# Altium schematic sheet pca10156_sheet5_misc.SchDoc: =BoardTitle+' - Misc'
size A3; Organization: Nordic Semiconductor; DocumentNumber: 5; SheetNumber: 5; SheetTotal: 8; CompanyName: Nordic Semiconductor; DocumentSize: A4
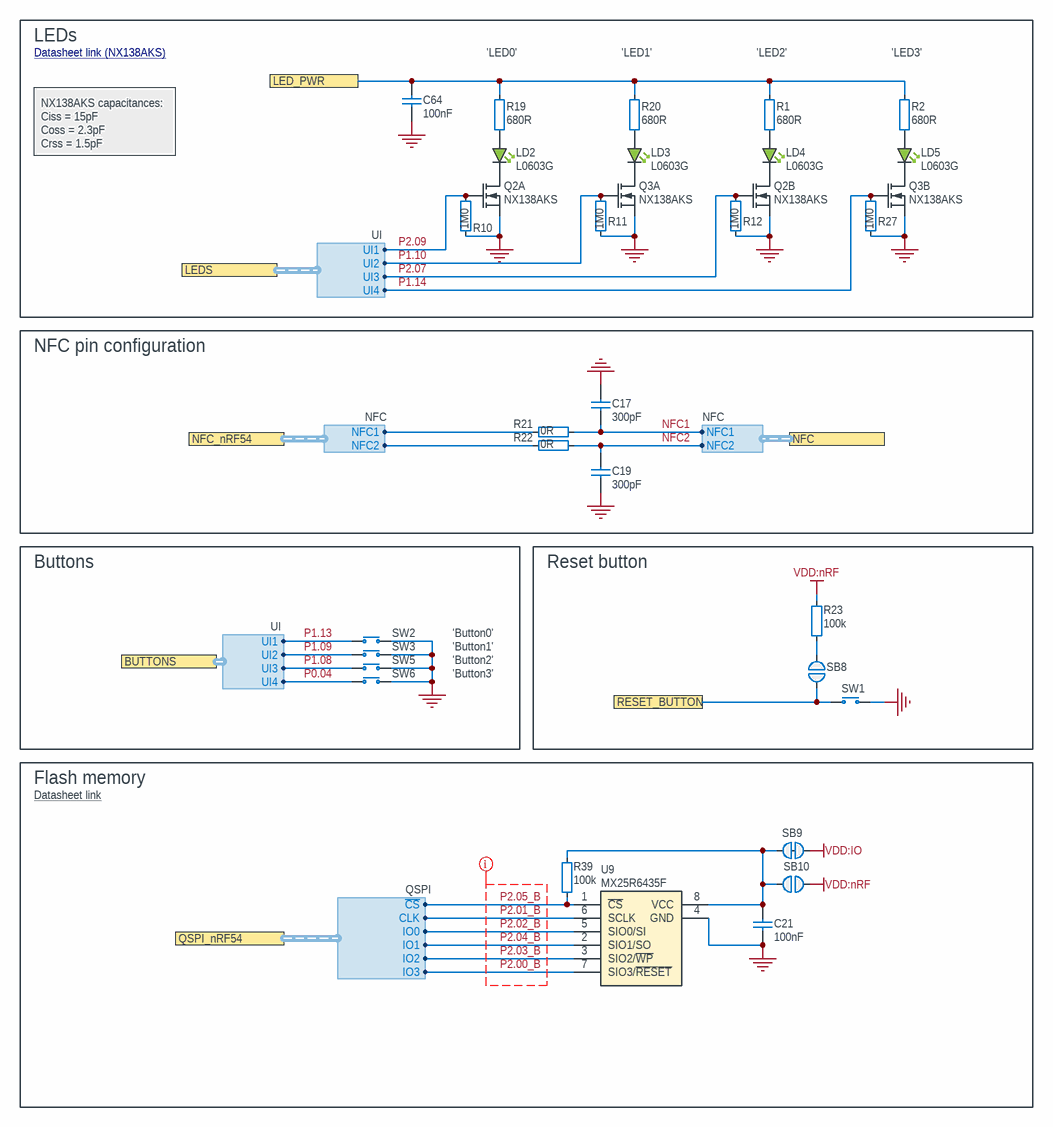
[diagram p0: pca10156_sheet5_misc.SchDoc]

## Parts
C17  300pF  [CAPC1005X04L]
C19  300pF  [CAPC1005X04L]
C21  100nF  [CAPC0603X03L_C]
C64  100nF  [CAPC0603X03L_C]
LD2  L0603G  [LED_0603_G]
LD3  L0603G  [LED_0603_G]
LD4  L0603G  [LED_0603_G]
LD5  L0603G  [LED_0603_G]
Q2  NX138AKS  [TSSOP6]  (parts A,B of 2)
Q3  NX138AKS  [TSSOP6]  (parts A,B of 2)
R1  680R  [RESC0603X03L_C]
R2  680R  [RESC0603X03L_C]
R10  1M0  [RESC0603X03L_C]
R11  1M0  [RESC0603X03L_C]
R12  1M0  [RESC0603X03L_C]
R19  680R  [RESC0603X03L_C]
R20  680R  [RESC0603X03L_C]
R21  0R  [RESC1005X04L]
R22  0R  [RESC1005X04L]
R23  100k  [RESC0603X03L_C]
R27  1M0  [RESC0603X03L_C]
R39  100k  [RESC0603X03L_C]
SB8  Solderbridge  [Solderbridge]  (value not drawn)  (no BOM)
SB9  Solderbridge  [Solderbridge_Shorted]  (value not drawn)  (net tie, no BOM)
SB10  Solderbridge  [Solderbridge]  (value not drawn)  (no BOM)
SW1  PB SW  [Switch-PB-6.2x6.3mm-SMD]  (value not drawn)
SW2  PB SW  [Switch-PB-6.2x6.3mm-SMD]  (value not drawn)
SW3  PB SW  [Switch-PB-6.2x6.3mm-SMD]  (value not drawn)
SW5  PB SW  [Switch-PB-6.2x6.3mm-SMD]  (value not drawn)
SW6  PB SW  [Switch-PB-6.2x6.3mm-SMD]  (value not drawn)
U9  MX25R6435F  [SON127P600X80_HS-9N]

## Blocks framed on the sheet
LEDs: C64 LD2-LD5 Q2 Q3 R1 R2 R10-R12 R19 R20 R27
NFC pin configuration: C17 C19 R21 R22
Buttons: SW2 SW3 SW5 SW6
Reset button: R23 SB8 SW1
Flash memory: C21 R39 SB9 SB10 U9

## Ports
BUTTONS (harness UI), LED_PWR, LEDS (harness UI), NFC (harness NFC), NFC_nRF54 (harness NFC), QSPI_nRF54 (harness QSPI), RESET_BUTTON

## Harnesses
NFC: NFC2, NFC1
UI: UI2, UI1, UI3, UI4
UI: UI2, UI3, UI4, UI1
QSPI: ~{CS}, IO0, CLK, IO1, IO2, IO3

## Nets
GND: C17.2 C19.1 C21.2 C64.1 Q2.1(S1) Q2.4(S2) Q3.1(S1) Q3.4(S2) R10.2 R11.2 R12.2 R27.2 SW1.1(N.O) SW2.1(N.O) SW3.1(N.O) SW5.1(N.O) SW6.1(N.O) U9.4(GND) U9.9(GND)
VDD:IO: SB9.1
VDD:nRF: R23.2 SB10.1
LED_PWR: C64.2 R1.2 R2.2 R19.2 R20.2 ; port LED_PWR
NFC1: C17.1 R21.2 ; port NFC.NFC1
NFC2: C19.2 R22.2 ; port NFC.NFC2
P0.04: SW6.2(COM) ; port BUTTONS.UI4
P1.08: SW5.2(COM) ; port BUTTONS.UI3
P1.09: SW3.2(COM) ; port BUTTONS.UI2
P1.10: Q3.2(G1) R11.1 ; port LEDS.UI2
P1.13: SW2.2(COM) ; port BUTTONS.UI1
P1.14: Q3.5(G2) R27.1 ; port LEDS.UI4
P2.00_B: U9.7(SIO3/~{RESET}) ; port QSPI_nRF54.IO3
P2.01_B: U9.6(SCLK) ; port QSPI_nRF54.CLK
P2.02_B: U9.5(SIO0/SI) ; port QSPI_nRF54.IO0
P2.03_B: U9.3(SIO2/~{WP}) ; port QSPI_nRF54.IO2
P2.04_B: U9.2(SIO1/SO) ; port QSPI_nRF54.IO1
P2.05_B: R39.1 U9.1(~{CS}) ; port QSPI_nRF54.~{CS}
P2.07: Q2.5(G2) R12.1 ; port LEDS.UI3
P2.09: Q2.2(G1) R10.1 ; port LEDS.UI1
RESET_BUTTON: SB8.1 SW1.2(COM) ; port RESET_BUTTON
NetC21_1: C21.1 R39.2 SB9.2 SB10.2 U9.8(VCC)
NetLD2_1: LD2.1(C) Q2.6(D1)
NetLD2_2: LD2.2(A) R19.1
NetLD3_1: LD3.1(C) Q3.6(D1)
NetLD3_2: LD3.2(A) R20.1
NetLD4_1: LD4.1(C) Q2.3(D2)
NetLD4_2: LD4.2(A) R1.1
NetLD5_1: LD5.1(C) Q3.3(D2)
NetLD5_2: LD5.2(A) R2.1
NetR21_1: R21.1 ; port NFC_nRF54.NFC1
NetR22_1: R22.1 ; port NFC_nRF54.NFC2
NetR23_1: R23.1 SB8.2

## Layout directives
net class QSPI: P2.00_B, P2.01_B, P2.02_B, P2.03_B, P2.04_B, P2.05_B

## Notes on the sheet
- Datasheet link (NX138AKS) <https://assets.nexperia.com/documents/data-sheet/NX138AKS.pdf>
- (near R19) 'LED0'
- (near R20) 'LED1'
- (near R1) 'LED2'
- (near R2) 'LED3'
- NX138AKS capacitances:
  Ciss = 15pF
  Coss = 2.3pF
  Crss = 1.5pF
- 'Button0'
- 'Button1'
- 'Button2'
- 'Button3'
- Datasheet link <https://www.mxic.com.tw/Lists/Datasheet/Attachments/8868/MX25R6435F,%20Wide%20Range,%2064Mb,%20v1.6.pdf>

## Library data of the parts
C17 C19 = C0402-300p: Capacitor, C0G, ±5%, 50V; Manufacturer: N.A.; Part number IPS: 00000007788; Part number NEMS: 100200155; Artikkelnr Noca: 20020004; Pad Count: 2; Component Status: Active
C21 = C0201-100n: Capacitor, X5R, ±10%; Manufacturer: N.A.; Part number IPS: 00000001248, 00000002505; Part number Norautron: 262071862; Part number NEMS: 100200078; Pad Count: 2; Note: 16V; Component Status: Active
C64 = C0201-100n: Capacitor, X5R, ±10%; Manufacturer: N.A.; Part number IPS: 00000001248, 00000002505; Part number Norautron: 262071862; Part number NEMS: 100200078; Note: 16V; Pad Count: 2; Component Status: Active
LD2-LD5 = VS 25C7M5: LED, Green, 0603, 573nm, Vf=2.0V, 24mcd, - 40 to +85°C; Manufacturer: Victory Electronics; Part number IPS: 00000001274, 00000009961; Part number Norautron: 26313411; Part number NEMS: 101400097; Pad Count: 2; Note: N.A.; Artikkelnr Noca: 13019193; Component Status: Active
Q2 Q3 = NX138AKS: MOSFET 2N-CH 60V 0.17A TSSOP6 (SOT363); Manufacturer: Nexperia; Manufacturer Part Number: NX138AKSX; Part number NEMS: 101300207; Component Status: Active; Pad Count: 6; Note: N.A.
R1 R2 R19 R20 = R0201-680: Resistor, ±1%, 0.05W; Manufacturer: N.A.; Part number NEMS: 100100040; Component Status: Active; Pad Count: 2; Note: Chip Res 1%
R10-R12 R27 = R0201-1M0: Resistor, ±1%, 0.05W; Manufacturer: N.A.; Part number IPS: 00000001418; Part number Norautron: 26107108; Part number NEMS: 100100093; Component Status: Active; Pad Count: 2; Note: Chip Res 1%
R21 R22 = R0402-0R: Resistor, ±5%, 0.063W; Manufacturer: N.A.; Part number IPS: 00000007128; Part number NEMS: 100100109; Component Status: Active; Pad Count: 2; Note: Chip Res 5%; Artikkelnr Noca: 27049000
R23 R39 = R0201-100k: Resistor, ±1%, 0.05W; Manufacturer: N.A.; Part number IPS: 00000001419; Part number Norautron: 26108487; Part number NEMS: 100100080; Note: Chip Res 1%; Pad Count: 2; Component Status: Active
SB8 SB10 = Solderbridge: Manufacturer: N.A.; Part number NEMS: 100500458; Pad Count: 2; Component Status: Active; System: Connector
SB9 = Solderbridge Shorted: Shorted Solderbridge; Manufacturer: N.A.; Part number NEMS: 100500459; Pad Count: 2; Component Status: Active; System: Connector
SW1-SW3 SW5 SW6 = Switch-PB-6.2x6.3mm-SMD: Tactile Switch, SPNO, SMD, 160gf, 6.2x6.3x2.5mm; Manufacturer: Dailywell; Manufacturer Part Number: TS604VM1-025BR-R; Part number IPS: 00000007812; Part number NEMS: 101500001, 101500133; Note: N.A.; Artikkelnr Noca: 50019106; Pad Count: 4; Component Status: Active
U9 = MX25R6435FZNIL0: Ultra low power, 64M-bit, serial multi I/O flash memory; Manufacturer: Macronix; Part number IPS: 00000004370; Part number NEMS: 101900438; Note: N.A.; Artikkelnr Noca: 15020015; Pad Count: 8; Component Status: Active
